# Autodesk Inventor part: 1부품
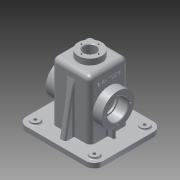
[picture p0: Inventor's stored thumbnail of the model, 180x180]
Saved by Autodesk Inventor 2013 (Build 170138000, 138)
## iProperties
Created: 2016-01
Part Number: 1부품
Material: 알루미늄 6061
Document SubType Name: Modeling
Designer: Administrator
Density: 2.71 g/cm^3
Mass: 808.405 g
Surface Area: 920.161 cm^2
Volume: 298.305 cm^3
Author: Administrator
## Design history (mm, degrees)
sketch "스케치1"
  geometry: L1 (-65, 57.5)-(65, 57.5); L2 (65, 57.5)-(65, -57.5); L3 (65, -57.5)-(-65, -57.5); L4 (-65, -57.5)-(-65, 57.5); L5 (-65, 57.5)-(65, -57.5); L6 (65, 57.5)-(-65, -57.5); 1 further point
  constraints: 12 end point, 2 midpoint, 2 parallel, 1 horizontal, 1 perpendicular
  dimensions: "d0" = 130 distance of L2.end L3.end; "d2" = 115 distance of L1.end L2.end
extrude "돌출1" new body sketch "스케치1" distance "d3" = 10; taper "d4" = 0 deg
fillet "모깎기1" dims "d5" = 15
sketch "스케치2"
  geometry: L1 (-32.5, 32.5)-(32.5, 32.5); L2 (32.5, 32.5)-(32.5, -32.5); L3 (32.5, -32.5)-(-32.5, -32.5); L4 (-32.5, -32.5)-(-32.5, 32.5); L5 (-32.5, 32.5)-(32.5, -32.5); L6 (32.5, 32.5)-(-32.5, -32.5); 1 further point
  constraints: 12 end point, 2 midpoint, 2 parallel, 1 horizontal, 1 perpendicular
  dimensions: "d6" = 65 distance of L1.start L1.end; "d8" = 65 distance of L1.end L2.end
extrude "돌출2" join sketch "스케치2" distance "d9" = 100; taper "d10" = 0 deg
fillet "모깎기2" dims "d11" = 8
sketch "스케치3"
  geometry: L1 (65, -42.5)-(65, 42.5) reference; L2 (50, 57.5)-(-50, 57.5) reference; L3 (-65, 42.5)-(-65, -42.5) reference; L4 (-50, -57.5)-(50, -57.5) reference; L5 (-50, -52.5)-(50, -52.5); L6 (60, -42.5)-(60, 42.5); L7 (50, 52.5)-(-50, 52.5); L8 (-60, 42.5)-(-60, -42.5); L9 (-60, -52.5)-(60, 52.5); L10 (60, -52.5)-(-60, 52.5); A1 r 15 centre (50, -42.5) between (50, -57.5) and (65, -42.5) reference; A2 r 15 centre (50, 42.5) between (65, 42.5) and (50, 57.5) reference; A3 r 15 centre (-50, 42.5) between (-50, 57.5) and (-65, 42.5) reference; A4 r 15 centre (-50, -42.5) between (-65, -42.5) and (-50, -57.5) reference; A5 r 10 centre (-50, -42.5) between (-60, -42.5) and (-50, -52.5); A6 r 10 centre (50, -42.5) between (50, -52.5) and (60, -42.5); A7 r 10 centre (50, 42.5) between (60, 42.5) and (50, 52.5); A8 r 10 centre (-50, 42.5) between (-50, 52.5) and (-60, 42.5); 1 further point
  constraints: 12 end point, 8 point on circle, 8 point on line, 8 tangent, 4 centre point, 3 equal radius, 2 midpoint, 2 parallel, 1 horizontal, 1 perpendicular
  dimensions: "d13" = 120 distance of L9.end L10.end; "d15" = 105 distance of L10.end L9.start; "d16" = 10 radius of A5
extrude "돌출3" cut sketch "스케치3" distance "d17" = 2; taper "d18" = 0 deg
sketch "스케치4"
  geometry: L1 (-24.5, -27.5)-(24.5, -27.5); L2 (27.5, -24.5)-(27.5, 24.5); L3 (24.5, 27.5)-(-24.5, 27.5); L4 (-27.5, 24.5)-(-27.5, -24.5); L5 (-27.5, -27.5)-(27.5, 27.5); L6 (27.5, -27.5)-(-27.5, 27.5); A1 r 3 centre (-24.5, -24.5) between (-27.5, -24.5) and (-24.5, -27.5); A2 r 3 centre (24.5, -24.5) between (24.5, -27.5) and (27.5, -24.5); A3 r 3 centre (24.5, 24.5) between (27.5, 24.5) and (24.5, 27.5); A4 r 3 centre (-24.5, 24.5) between (-24.5, 27.5) and (-27.5, 24.5); 1 further point
  constraints: 12 end point, 8 point on circle, 8 point on line, 8 tangent, 4 centre point, 3 equal radius, 2 midpoint, 2 parallel, 1 horizontal, 1 perpendicular
  dimensions: "d19" = 55 distance of L6.end L5.start; "d21" = 55 distance of L5.end L6.end; "d22" = 3 radius of A1
extrude "돌출4" cut sketch "스케치4" distance "d23" = 105; taper "d24" = 0 deg
fillet "모깎기3" dims "d25" = 3
sketch "스케치5"
  geometry: C1 r 20 at (0, 0); 1 further point
  constraints: 1 centre point, 1 coincident
  dimensions: "d26" = 40 diameter of C1
extrude "돌출5" join sketch "스케치5" distance "d27" = 10; taper "d28" = 0 deg
hole "구멍1" diameter "d31" = 21; stored, may be unused: countersink angle "d35" = 90 deg, drill point angle "d37" = 118 deg; dims "d29" = 10, "d30" = 10, "d32" = 6, "d33" = 4, "d34" = 2, "d36" = 8
sketch "스케치6"
  geometry: C1 r 10.5 at (0, 0) reference; 1 further point
  constraints: 1 vertical alignment
  dimensions: "d38" = 14.5 distance of C1.centre point (0, 14.5)
hole "구멍2" sketch "스케치6" at (0, 14.5) diameter "d39" = 2.459; stored, may be unused: countersink angle "d43" = 90 deg, drill point angle "d45" = 118 deg; dims "d40" = 7, "d41" = 4, "d42" = 2, "d44" = 9
sketch "스케치7"
  geometry: L1 (-52.5, 0)-(-52.5, 2) reference; L2 (-52.5, 2)-(-57.5, 2) reference; L3 (-57.5, 2)-(-57.5, 10) reference; L4 (-57.5, 10)-(-32.5, 10) reference; L5 (-32.5, 10)-(-32.5, 110) reference; L6 (-32.5, 110)-(-20, 110) reference; L7 (-20, 110)-(-20, 120) reference; L8 (-20, 120)-(-15.73, 120) reference; L9 (-15.73, 120)-(-15.73, 111) reference; L10 (-15.73, 111)-(-14.5, 110.261) reference; L11 (-14.5, 110.261)-(-13.271, 111) reference; L12 (-13.271, 111)-(-13.271, 120) reference; L13 (-13.271, 120)-(-10.5, 120) reference; L14 (-10.5, 120)-(-10.5, 105) reference; L15 (-10.5, 105)-(-24.5, 105) reference; L16 (-27.5, 102)-(-27.5, 0) reference; L17 (-27.5, 0)-(-52.5, 0) reference; L18 (32.5, 110)-(32.5, 10) reference; L19 (32.5, 10)-(57.5, 10) reference; L20 (57.5, 10)-(57.5, 2) reference; L21 (57.5, 2)-(52.5, 2) reference; L22 (52.5, 2)-(52.5, 0) reference; L23 (52.5, 0)-(27.5, 0) reference; L24 (27.5, 0)-(27.5, 102) reference; L25 (24.5, 105)-(10.5, 105) reference; L26 (10.5, 105)-(10.5, 120) reference; L27 (10.5, 120)-(13.271, 120) reference; L28 (13.271, 120)-(13.271, 111) reference; L29 (13.271, 111)-(14.5, 110.261) reference; L30 (14.5, 110.261)-(15.73, 111) reference; L31 (15.73, 111)-(15.73, 120) reference; L32 (15.73, 120)-(20, 120) reference; L33 (20, 120)-(20, 110) reference; L34 (20, 110)-(32.5, 110) reference; C1 r 27.5 at (0, 55); A1 r 3 centre (-24.5, 102) between (-24.5, 105) and (-27.5, 102) reference; A2 r 3 centre (24.5, 102) between (27.5, 102) and (24.5, 105) reference; 1 further point
  constraints: 1 centre point, 1 vertical alignment
  dimensions: "d49" = 55 diameter of C1; "d50" = 55 distance of point (0, 0) C1.centre
extrude "돌출6" join sketch "스케치7" stored distance "d51" = 95; taper "d52" = 0 deg
hole "구멍3" diameter "d55" = 30; stored, may be unused: countersink angle "d59" = 90 deg, drill point angle "d61" = 0 deg; dims "d56" = 7, "d57" = 35, "d58" = 17, "d60" = 9, "d62" = 10, "d63" = 10
sketch "스케치8"
  geometry: C1 r 17.5 at (0, 0) reference; 2 further points
  constraints: 1 horizontal alignment
  dimensions: "d64" = 21 distance of C1.centre point (-21, 0)
hole "구멍4" sketch "스케치8" at (-21, 0) diameter "d65" = 3.242; stored, may be unused: countersink angle "d69" = 90 deg, drill point angle "d71" = 118 deg; dims "d66" = 8, "d67" = 42, "d68" = 17, "d70" = 10
sketch "스케치9"
  geometry: L1 (-20, 110)-(-20, 120) reference; L2 (-20, 120)-(-15.73, 120) reference; L3 (-15.73, 120)-(-15.73, 111) reference; L4 (-15.73, 111)-(-14.5, 110.261) reference; L5 (-14.5, 110.261)-(-13.271, 111) reference; L6 (-13.271, 111)-(-13.271, 120) reference; L7 (-13.271, 120)-(-10.5, 120) reference; L8 (-10.5, 120)-(-10.5, 105) reference; L9 (-10.5, 105)-(-24.5, 105) reference; L10 (-27.5, 102)-(-27.5, 82.5) reference; L11 (-27.5, 82.5)-(27.5, 82.5) reference; L12 (27.5, 82.5)-(27.5, 102) reference; L13 (24.5, 105)-(10.5, 105) reference; L14 (10.5, 105)-(10.5, 120) reference; L15 (10.5, 120)-(13.271, 120) reference; L16 (13.271, 120)-(13.271, 111) reference; L17 (13.271, 111)-(14.5, 110.261) reference; L18 (14.5, 110.261)-(15.73, 111) reference; L19 (15.73, 111)-(15.73, 120) reference; L20 (15.73, 120)-(20, 120) reference; L21 (20, 120)-(20, 110) reference; L22 (20, 110)-(32.5, 110) reference; L23 (32.5, 110)-(32.5, 82.5) reference; L24 (32.5, 82.5)-(47.5, 82.5) reference; L25 (47.5, 82.5)-(47.5, 77.621) reference; L26 (47.5, 77.621)-(37.5, 77.621) reference; L27 (37.5, 77.621)-(36.526, 76) reference; L28 (37.5, 74.379)-(47.5, 74.379) reference; L29 (47.5, 74.379)-(47.5, 72.5) reference; L30 (47.5, 72.5)-(30.5, 72.5) reference; L31 (30.5, 72.5)-(30.5, 70) reference; L32 (30.5, 70)-(-30.5, 70) reference; L33 (-30.5, 70)-(-30.5, 72.5) reference; L34 (-30.5, 72.5)-(-47.5, 72.5) reference; L35 (-47.5, 72.5)-(-47.5, 74.379) reference; L36 (-47.5, 74.379)-(-37.5, 74.379) reference; L37 (-37.5, 74.379)-(-36.526, 76) reference; L38 (-37.5, 77.621)-(-47.5, 77.621) reference; L39 (-47.5, 77.621)-(-47.5, 82.5) reference; L40 (-47.5, 82.5)-(-32.5, 82.5) reference; L41 (-32.5, 82.5)-(-32.5, 110) reference; L42 (-32.5, 110)-(-20, 110) reference; L43 (-60, 0)-(-60, 2) reference; L44 (-60, 2)-(-65, 2) reference; L45 (-65, 2)-(-65, 10) reference; L46 (-65, 10)-(-32.5, 10) reference; L47 (-32.5, 10)-(-32.5, 27.5) reference; L48 (-32.5, 27.5)-(-47.5, 27.5) reference; L49 (-47.5, 27.5)-(-47.5, 32.379) reference; L50 (-47.5, 32.379)-(-37.5, 32.379) reference; L51 (-37.5, 32.379)-(-36.526, 34) reference; L52 (-37.5, 35.621)-(-47.5, 35.621) reference; L53 (-47.5, 35.621)-(-47.5, 37.5) reference; L54 (-47.5, 37.5)-(-30.5, 37.5) reference; L55 (-30.5, 37.5)-(-30.5, 40) reference; L56 (-30.5, 40)-(30.5, 40) reference; L57 (30.5, 40)-(30.5, 37.5) reference; L58 (30.5, 37.5)-(47.5, 37.5) reference; L59 (47.5, 37.5)-(47.5, 35.621) reference; L60 (47.5, 35.621)-(37.5, 35.621) reference; L61 (37.5, 35.621)-(36.526, 34) reference; L62 (37.5, 32.379)-(47.5, 32.379) reference; L63 (47.5, 32.379)-(47.5, 27.5) reference; L64 (47.5, 27.5)-(32.5, 27.5) reference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; A1 r 3 centre (-24.5, 102) between (-24.5, 105) and (-27.5, 102) reference; A2 r 3 centre (24.5, 102) between (27.5, 102) and (24.5, 105) reference; 1 further point
  constraints: 4 end point, 4 point on line, 2 perpendicular, 1 parallel
  dimensions: "d75" = 15 distance between parallel lines of L75 L71; "d76" = 15 distance between parallel lines of L76 L73
extrude "돌출7" join sketch "스케치9" stored distance "d77" = 6; taper "d78" = 0 deg
sketch "스케치10"
  geometry: L1 (-52.5, 0)-(-52.5, 2) reference; L2 (-52.5, 2)-(-57.5, 2) reference; L3 (-57.5, 2)-(-57.5, 10) reference; L4 (-57.5, 10)-(-32.5, 10) reference; L5 (-32.5, 10)-(-32.5, 110) reference; L6 (-32.5, 110)-(-20, 110) reference; L7 (-20, 110)-(-20, 120) reference; L8 (-20, 120)-(-15.73, 120) reference; L9 (-15.73, 120)-(-15.73, 111) reference; L10 (-15.73, 111)-(-14.5, 110.261) reference; L11 (-14.5, 110.261)-(-13.271, 111) reference; L12 (-13.271, 111)-(-13.271, 120) reference; L13 (-13.271, 120)-(-10.5, 120) reference; L14 (-10.5, 120)-(-10.5, 105) reference; L15 (-10.5, 105)-(-24.5, 105) reference; L16 (-27.5, 102)-(-27.5, 55) reference; L17 (27.5, 0)-(27.5, 55) reference; L18 (52.5, 0)-(27.5, 0) reference; L19 (52.5, 2)-(52.5, 0) reference; L20 (57.5, 2)-(52.5, 2) reference; L21 (57.5, 10)-(57.5, 2) reference; L22 (32.5, 10)-(57.5, 10) reference; L23 (32.5, 110)-(32.5, 10) reference; L24 (20, 110)-(32.5, 110) reference; L25 (20, 120)-(20, 110) reference; L26 (15.73, 120)-(20, 120) reference; L27 (15.73, 111)-(15.73, 120) reference; L28 (14.5, 110.261)-(15.73, 111) reference; L29 (13.271, 111)-(14.5, 110.261) reference; L30 (13.271, 120)-(13.271, 111) reference; L31 (10.5, 120)-(13.271, 120) reference; L32 (10.5, 105)-(10.5, 120) reference; L33 (24.5, 105)-(10.5, 105) reference; L34 (27.5, 55)-(27.5, 102) reference; L35 (-27.5, 0)-(-52.5, 0) reference; L36 (-27.5, 55)-(-27.5, 0) reference; L37 (-32.5, 95.069)-(-47.5, 10); L38 (32.5, 95.069)-(47.5, 10); C1 r 15 at (0, 55) reference; A1 r 3 centre (-24.5, 102) between (-24.5, 105) and (-27.5, 102) reference; A2 r 27.5 centre (0, 55) between (27.5, 55) and (-27.5, 55) reference; A3 r 3 centre (24.5, 102) between (27.5, 102) and (24.5, 105) reference; A4 r 27.5 centre (0, 55) between (-27.5, 55) and (27.5, 55) reference; 1 further point
  constraints: 4 end point, 4 point on line
  dimensions: "d79" = 10 deg angle of L3 L37; "d80" = 10 distance of L37.end L3.end; "d81" = 10 distance of L21.start L38.end; "d82" = 100 deg angle of L22 L38
extrude "돌출8" join sketch "스케치10" stored distance "d83" = 10; taper "d84" = 0 deg
sketch "스케치11"
  geometry: C1 r 7.5 at (-50, 42.5); C2 r 7.5 at (50, 42.5); C3 r 7.5 at (50, -42.5); C4 r 7.5 at (-50, -42.5); A1 r 15 centre (-50, -42.5) between (-65, -42.5) and (-50, -57.5) reference; A2 r 15 centre (50, -42.5) between (50, -57.5) and (65, -42.5) reference; A3 r 15 centre (50, 42.5) between (65, 42.5) and (50, 57.5) reference; A4 r 15 centre (-50, 42.5) between (-50, 57.5) and (-65, 42.5) reference; 1 further point
  constraints: 4 centre point, 4 coincident
  dimensions: "d85" = 15 diameter of C1; "d86" = 15 diameter of C2; "d87" = 15 diameter of C3; "d88" = 15 diameter of C4
extrude "돌출9" join sketch "스케치11" distance "d89" = 3; taper "d90" = 0 deg
sketch "스케치12"
  geometry: L1 (-82.5, 39.5)-(-92.5, 39.5) reference; L2 (-92.5, 39.5)-(-92.5, 45.5) reference; L3 (-92.5, 45.5)-(-82.5, 45.5) reference; L4 (-82.5, 45.5)-(-82.5, 67) reference; L5 (-74.5, 75)-(-55, 75) reference; L6 (-55, 75)-(-55, 89.471) reference; L7 (-55, 89.471)-(-45, 89.471) reference; L8 (-45, 89.471)-(-45, 75) reference; L9 (-45, 75)-(-25.5, 75) reference; L10 (-17.5, 67)-(-17.5, 45.5) reference; L11 (-17.5, 45.5)-(-7.5, 45.5) reference; L12 (-7.5, 45.5)-(-7.5, 39.5) reference; L13 (-7.5, 39.5)-(-17.5, 39.5) reference; L14 (-17.5, 39.5)-(-17.5, 18) reference; L15 (-25.5, 10)-(-45, 10) reference; L16 (-45, 10)-(-45, -4.471) reference; L17 (-45, -4.471)-(-55, -4.471) reference; L18 (-55, -4.471)-(-55, 10) reference; L19 (-55, 10)-(-74.5, 10) reference; L20 (-82.5, 18)-(-82.5, 39.5) reference; L21 (-25.5, 70)-(-74.5, 70) reference; L22 (-77.5, 67)-(-77.5, 18) reference; L23 (-74.5, 15)-(-25.5, 15) reference; L24 (-22.5, 18)-(-22.5, 67) reference; C1 r 7.5 at (0, 0) reference; C2 r 7.5 at (0, 0) reference; C3 r 7.5 at (-100, 85) reference; C4 r 7.5 at (0, 85) reference; C5 r 7.5 at (-100, 0) reference; A1 r 8 centre (-74.5, 67) between (-74.5, 75) and (-82.5, 67) reference; A2 r 8 centre (-25.5, 67) between (-17.5, 67) and (-25.5, 75) reference; A3 r 8 centre (-25.5, 18) between (-25.5, 10) and (-17.5, 18) reference; A4 r 8 centre (-74.5, 18) between (-82.5, 18) and (-74.5, 10) reference; A5 r 3 centre (-25.5, 67) between (-22.5, 67) and (-25.5, 70) reference; A6 r 3 centre (-74.5, 67) between (-74.5, 70) and (-77.5, 67) reference; A7 r 3 centre (-74.5, 18) between (-77.5, 18) and (-74.5, 15) reference; A8 r 3 centre (-25.5, 18) between (-25.5, 15) and (-22.5, 18) reference; 1 further point
hole "구멍5" sketch "스케치12" at (-100, 0), (-100, 85), (0, 0), (0, 85) diameter "d91" = 5; stored, may be unused: countersink angle "d95" = 90 deg, drill point angle "d97" = 0 deg; dims "d92" = 8, "d93" = 42, "d94" = 17, "d96" = 10
sketch "스케치13"
  geometry: L1 (0, -8)-(100, -8) reference; L2 (-10, 44.5)-(-10, 4.5) reference; 2 further points
  constraints: 1 other
  dimensions: "d98" = 32.5 distance from line of point (17, 24.5) L1; "d99" = 27 distance from line of point (17, 24.5) L2
feature "엠보싱1" sketch "스케치13" dims "d0" = 130, "d2" = 115, "d100" = 0.5, "d101" = 0
fillet "모깎기4" dims "d102" = 8
chamfer "모따기1" distance "d103" = 1; stored, may be unused: second distance "d104" = 2, angle "d105" = 45 deg
fillet "모깎기5" dims "d106" = 0.3
fillet "모깎기6" dims "d107" = 3
fillet "모깎기7" dims "d112" = 2
sketch "스케치14"
  geometry: L1 (-27.5, -24.5)-(-27.5, 24.5) reference; L2 (-24.5, 27.5)-(24.5, 27.5) reference; L3 (27.5, 24.5)-(27.5, -24.5) reference; L4 (24.5, -27.5)-(-24.5, -27.5) reference; L5 (24.5, 27.5)-(-24.5, 27.5); L6 (-27.5, 24.5)-(-27.5, -24.5); L7 (-24.5, -27.5)-(24.5, -27.5); L8 (27.5, -24.5)-(27.5, 24.5); A1 r 3 centre (-24.5, -24.5) between (-27.5, -24.5) and (-24.5, -27.5) reference; A2 r 3 centre (-24.5, 24.5) between (-24.5, 27.5) and (-27.5, 24.5) reference; A3 r 3 centre (24.5, 24.5) between (27.5, 24.5) and (24.5, 27.5) reference; A4 r 3 centre (24.5, -24.5) between (24.5, -27.5) and (27.5, -24.5) reference; A5 r 3 centre (-24.5, 24.5) between (-24.5, 27.5) and (-27.5, 24.5); A6 r 3 centre (-24.5, -24.5) between (-27.5, -24.5) and (-24.5, -27.5); A7 r 3 centre (24.5, -24.5) between (24.5, -27.5) and (27.5, -24.5); A8 r 3 centre (24.5, 24.5) between (27.5, 24.5) and (24.5, 27.5); 1 further point
  constraints: 8 end point, 8 point on circle, 4 centre point, 7 other
  dimensions: "d109" = 0 distance between parallel lines of L5 L2
extrude "돌출10" cut sketch "스케치14" distance "d110" = 100; taper "d111" = 0 deg
fillet "모깎기8" dims "d113" = 1
node "솔리드1"
pattern_circular "원형 패턴1" dims angle "d47" = 360 deg
mirror "대칭1"
pattern_circular "원형 패턴2" dims angle "d73" = 360 deg
mirror "대칭2"
node "절단 모서리 투영1"
node "절단 모서리 투영2"
node "절단 모서리 투영3"
node "절단 모서리 투영4"
